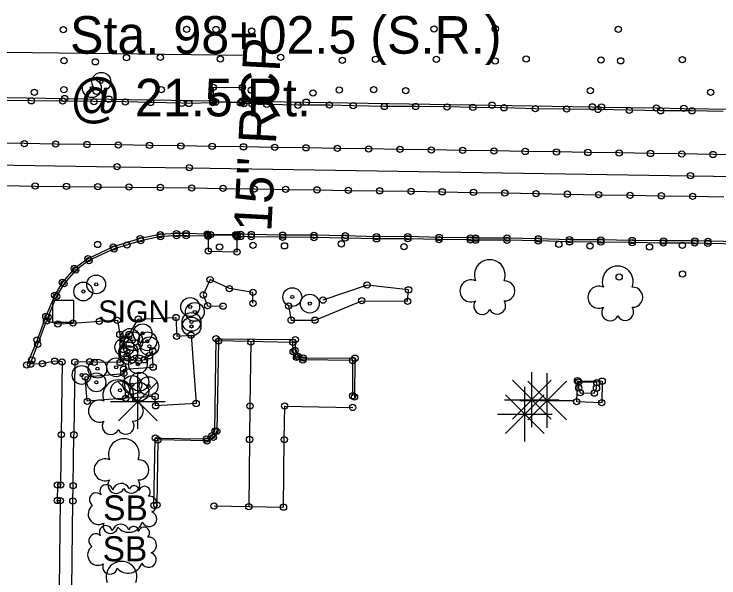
# Model space of a CAD drawing. Extents: x 20503438 to 20508873, y 7964251 to 7984667.
# Drawn here: x 20504811.1 to 20505036.2, y 7970431.1 to 7970611 of the extents above; entities that cross this region are included whole.
import ezdxf

# ---------------------------------------------------------------- set-up
doc = ezdxf.new("R2010")
doc.units = 0
for name, color, linetype in [('SurBreakLine', 7, 'Continuous'), ('SurConcreteSlab', 7, 'Continuous'), ('SurEdgeCurb', 7, 'Continuous'), ('SurEdgeRoadPaved', 7, 'Continuous'), ('SurEdgeSidewalk', 7, 'Continuous'), ('SurFenceWire', 7, 'Continuous'), ('SurHedge', 7, 'Continuous'), ('SurMiscStructureLine', 7, 'Continuous'), ('SurNaturalCells', 7, 'Continuous'), ('SurPointsNonDTM', 7, 'Continuous'), ('SurRoadPoints', 7, 'Continuous'), ('SurSurveyPoints', 7, 'Continuous'), ('SurTxtDrainage', 7, 'Continuous')]:
    doc.layers.add(name, color=color, linetype=linetype)

msp = doc.modelspace()

# ---------------------------------------------------------------- linework, layer by layer
at = {"layer": 'SurBreakLine'}
msp.add_lwpolyline([(20504771.9, 7970563.37), (20504797.86, 7970563), (20504843.99, 7970562.34), (20504867.04, 7970562.01), (20505027.11, 7970559.46), (20505056.57, 7970559.02), (20505122.33, 7970557.99), (20505134.3, 7970557.78), (20505181.34, 7970557.02), (20505190.04, 7970556.88), (20505298.19, 7970555.19), (20505381.79, 7970553.77), (20505481.65, 7970551.95), (20505538.21, 7970551.74), (20505602.69, 7970550.28), (20505659.98, 7970549.19), (20505725.91, 7970548.38)], dxfattribs=at)
at = {"layer": 'SurConcreteSlab'}
for points in [[(20504874.77, 7970583.05), (20504874.76, 7970587.67), (20504884.01, 7970587.63), (20504883.93, 7970582.84)], [(20504873.07, 7970540.53), (20504873.12, 7970535.41), (20504882.33, 7970535.14), (20504882.33, 7970540.34)], [(20504850.78, 7970513.69), (20504862.78, 7970514.2), (20504863.05, 7970508.22), (20504867.61, 7970508.56), (20504869.25, 7970486.75), (20504856.32, 7970486), (20504856.16, 7970488.98), (20504846.77, 7970488.43), (20504846.11, 7970497.7), (20504855.53, 7970498.36), (20504855.34, 7970503.57), (20504854.26, 7970501.98), (20504852.74, 7970500.7), (20504850.9, 7970500.28), (20504848.84, 7970500.61), (20504847.16, 7970501.86), (20504846.03, 7970504), (20504845.92, 7970505.68), (20504846.62, 7970507.38), (20504847.81, 7970508.81)], [(20504846.14, 7970496.36), (20504846.71, 7970488.42), (20504834.49, 7970487.47), (20504833.84, 7970495.26)], [(20504998.9, 7970493.88), (20504998.78, 7970486.99), (20504990.8, 7970487.3), (20504991.04, 7970494.03)]]:
    msp.add_lwpolyline(points, close=True, dxfattribs=at)
for points in [[(20505044.33, 7970566.08), (20505034.34, 7970566.24), (20505024.34, 7970566.4), (20505014.34, 7970566.56), (20505004.34, 7970566.72), (20504994.34, 7970566.88), (20504984.34, 7970567.04), (20504974.34, 7970567.2), (20504964.35, 7970567.36), (20504954.35, 7970567.53), (20504944.35, 7970567.69), (20504934.35, 7970567.86), (20504924.35, 7970568.02), (20504914.36, 7970568.18), (20504904.36, 7970568.35), (20504894.36, 7970568.51), (20504884.36, 7970568.68), (20504874.36, 7970568.83), (20504864.36, 7970568.97), (20504854.36, 7970569.12), (20504844.37, 7970569.27), (20504834.37, 7970569.42), (20504824.37, 7970569.57), (20504814.37, 7970569.72), (20504804.37, 7970569.87)], [(20504807.85, 7970556.29), (20504817.85, 7970556.17), (20504827.85, 7970556.05), (20504837.84, 7970555.94), (20504847.84, 7970555.82), (20504857.84, 7970555.71), (20504867.84, 7970555.55), (20504877.84, 7970555.4), (20504887.84, 7970555.25), (20504897.84, 7970555.09), (20504907.83, 7970554.94), (20504917.83, 7970554.78), (20504927.83, 7970554.63), (20504937.83, 7970554.48), (20504947.83, 7970554.32), (20504957.83, 7970554.13), (20504967.82, 7970553.95), (20504977.82, 7970553.76), (20504987.82, 7970553.58), (20504997.82, 7970553.39), (20505007.82, 7970553.21), (20505017.81, 7970553.05), (20505027.81, 7970552.9), (20505037.81, 7970552.75)], [(20504826.44, 7970500), (20504824.07, 7970500.26), (20504820.11, 7970499.45), (20504816.4, 7970499.3), (20504816.76, 7970500.66), (20504818.66, 7970505.66), (20504821.46, 7970513.14)], [(20504821.46, 7970513.14), (20504825.07, 7970512.13), (20504829.92, 7970512.42), (20504838.32, 7970512.99), (20504844.11, 7970513.33), (20504844.87, 7970508.76), (20504844.98, 7970499.83), (20504836.77, 7970499.92), (20504835.22, 7970500.07), (20504830.51, 7970499.97), (20504830.2, 7970476.76)], [(20504886.71, 7970506.41), (20504886.44, 7970485.96), (20504886.3, 7970475.27), (20504886.07, 7970453.85)], [(20504874.96, 7970454.04), (20504897.15, 7970453.65), (20504897.4, 7970475.22), (20504897.53, 7970485.95), (20504919.26, 7970485.49)]]:
    msp.add_lwpolyline(points, dxfattribs=at)
at = {"layer": 'SurEdgeCurb'}
for points in [[(20505037.59, 7970579.95), (20505027.59, 7970580.17), (20505017.59, 7970580.18), (20505007.59, 7970580.34), (20504997.59, 7970580.61), (20504987.59, 7970580.75), (20504977.59, 7970580.83), (20504967.6, 7970581.14), (20504957.6, 7970581.26), (20504949.37, 7970581.42), (20504939.37, 7970581.54), (20504929.37, 7970581.56), (20504919.38, 7970581.81), (20504911.81, 7970582), (20504901.81, 7970581.95), (20504891.81, 7970582.22), (20504887.15, 7970582.36), (20504884.51, 7970582.49), (20504883.4, 7970582.67), (20504875.45, 7970582.95), (20504874.56, 7970582.74), (20504866.97, 7970582.51), (20504864.69, 7970582.59), (20504854.69, 7970582.84), (20504846.61, 7970583.02), (20504836.61, 7970583.12), (20504826.61, 7970583.3), (20504816.61, 7970583.36), (20504807.55, 7970583.5)], [(20505042.68, 7970538.3), (20505032.68, 7970538.53), (20505028.5, 7970538.65), (20505018.49, 7970538.65), (20505008.49, 7970538.78), (20504998.49, 7970538.95), (20504988.49, 7970539.04), (20504978.5, 7970539.31), (20504968.5, 7970539.55), (20504958.49, 7970539.52), (20504956.87, 7970539.58), (20504946.85, 7970539.74), (20504936.86, 7970540.01), (20504926.86, 7970540), (20504916.86, 7970540.3), (20504906.86, 7970540.43), (20504896.86, 7970540.49), (20504886.86, 7970540.69), (20504883.43, 7970540.75), (20504882.42, 7970540.62), (20504881.88, 7970540.59), (20504873.92, 7970540.65), (20504872.81, 7970540.8), (20504866.07, 7970540.99), (20504862.96, 7970540.98), (20504857.78, 7970540.66), (20504851.38, 7970539.38), (20504842.8, 7970536.73), (20504834.7, 7970532.95), (20504830.35, 7970529.85), (20504826.5, 7970525.39), (20504824.07, 7970521.29), (20504821.26, 7970514.59), (20504818.45, 7970507), (20504815.13, 7970499.07)], [(20504873.07, 7970540.12), (20504866.07, 7970540.3), (20504862.99, 7970540.3), (20504857.88, 7970540.01), (20504851.54, 7970538.72), (20504843.05, 7970536.09), (20504835.03, 7970532.35), (20504830.79, 7970529.35), (20504827.07, 7970525.01), (20504824.68, 7970520.99), (20504821.93, 7970514.32), (20504821.46, 7970513.14)], [(20505042.66, 7970537.61), (20505032.67, 7970537.84), (20505028.48, 7970537.97), (20505018.48, 7970537.95), (20505008.48, 7970538.11), (20504998.48, 7970538.27), (20504988.48, 7970538.36), (20504978.48, 7970538.62), (20504968.49, 7970538.86), (20504958.49, 7970538.88), (20504956.84, 7970538.94), (20504946.84, 7970539.07), (20504936.84, 7970539.35), (20504926.84, 7970539.32), (20504916.84, 7970539.57), (20504906.85, 7970539.72), (20504896.85, 7970539.81), (20504886.85, 7970540), (20504883.49, 7970540.07), (20504882.33, 7970539.93)], [(20504855.77, 7970454.24), (20504856.18, 7970475.73), (20504872.49, 7970475.43), (20504874.33, 7970476.45), (20504875.24, 7970478), (20504875.59, 7970507.41), (20504900.91, 7970507.13), (20504900.83, 7970503.68), (20504901.72, 7970501.84), (20504903.45, 7970501.3), (20504919.96, 7970501.22), (20504919.83, 7970488.82)], [(20504919.26, 7970489.19), (20504919.25, 7970500.48), (20504903.31, 7970500.65), (20504901.3, 7970501.49), (20504900.23, 7970503.3), (20504900.13, 7970506.25), (20504876.44, 7970506.73), (20504875.84, 7970477.88), (20504874.77, 7970475.96), (20504872.74, 7970474.79), (20504857.03, 7970475.13), (20504856.71, 7970454.33)]]:
    msp.add_lwpolyline(points, dxfattribs=at)
at = {"layer": 'SurEdgeRoadPaved'}
for points in [[(20504727.85, 7970585.32), (20504737.85, 7970585.29), (20504744.25, 7970585.34), (20504754.25, 7970585.2), (20504764.26, 7970584.93), (20504772.2, 7970585.02), (20504827.27, 7970584.09), (20504841.35, 7970583.88), (20504874.77, 7970583.4)], [(20504883.94, 7970583.27), (20504904.39, 7970582.93), (20504963.72, 7970581.98), (20504995.8, 7970581.43), (20504998.71, 7970581.38), (20505016.18, 7970581.08), (20505025.01, 7970580.93), (20505048.57, 7970580.55), (20505051.52, 7970580.5), (20505057.41, 7970580.41), (20505084.04, 7970579.95), (20505175.4, 7970578.44)]]:
    msp.add_lwpolyline(points, dxfattribs=at)
at = {"layer": 'SurEdgeSidewalk'}
msp.add_lwpolyline([(20504826.44, 7970500), (20504826.17, 7970476.78), (20504825.95, 7970460.74), (20504824.96, 7970460.73), (20504824.89, 7970455.79), (20504825.87, 7970455.75), (20504825.55, 7970427.65), (20504829.53, 7970427.55), (20504829.88, 7970455.61), (20504829.97, 7970460.55), (20504830.2, 7970476.76)], dxfattribs=at)
at = {"layer": 'SurFenceWire'}
msp.add_lwpolyline([(20504884.71, 7970597.81), (20504782.91, 7970599.08), (20504566.31, 7970601.59), (20504471.49, 7970602.55)], dxfattribs=at)
at = {"layer": 'SurHedge'}
for points in [[(20504887.37, 7970518.73), (20504887.38, 7970522.2), (20504879.86, 7970523.43), (20504873.71, 7970526.29), (20504871.54, 7970521.42), (20504872.91, 7970517.95), (20504877.83, 7970517.82)], [(20504898.78, 7970517.9), (20504899.61, 7970513.36), (20504907.21, 7970513.34), (20504922.11, 7970519.56), (20504936.77, 7970519.39), (20504937.08, 7970523.04), (20504923.85, 7970524.54), (20504909.73, 7970519.75)]]:
    msp.add_lwpolyline(points, dxfattribs=at)
at = {"layer": 'SurMiscStructureLine'}
msp.add_lwpolyline([(20504991.35, 7970493.6), (20504991.38, 7970491.76), (20504991.89, 7970490.2), (20504996.4, 7970490.04), (20504997.11, 7970491.65), (20504997.22, 7970493.43)], close=True, dxfattribs=at)
at = {"layer": 'SurNaturalCells'}
for p, q in [((20504976.49, 7970479.23), (20504976.49, 7970496.71)), ((20504981.31, 7970478.97), (20504981.31, 7970496.45)), ((20504850.6, 7970478.67), (20504850.6, 7970496.15)), ((20504970.31, 7970481.79), (20504982.67, 7970494.15)), ((20504982.67, 7970481.79), (20504970.31, 7970494.15)), ((20504844.42, 7970481.23), (20504856.78, 7970493.59)), ((20504856.78, 7970481.23), (20504844.42, 7970493.59)), ((20504974.22, 7970474.59), (20504974.22, 7970492.07)), ((20504975.13, 7970481.53), (20504987.49, 7970493.89)), ((20504987.49, 7970481.53), (20504975.13, 7970493.89)), ((20504968.04, 7970477.15), (20504980.4, 7970489.51)), ((20504980.4, 7970477.15), (20504968.04, 7970489.51)), ((20504841.86, 7970487.41), (20504859.34, 7970487.41)), ((20504850.6, 7970487.41), (20504850.6, 7970487.41)), ((20504967.75, 7970487.97), (20504985.23, 7970487.97)), ((20504972.57, 7970487.71), (20504990.05, 7970487.71)), ((20504976.49, 7970487.97), (20504976.49, 7970487.97)), ((20504981.31, 7970487.71), (20504981.31, 7970487.71)), ((20504965.48, 7970483.33), (20504982.96, 7970483.33)), ((20504974.22, 7970483.33), (20504974.22, 7970483.33))]:
    msp.add_line(p, q, dxfattribs=at)
for centre, radius, start, end in [((20504963.02, 7970527.71), 4.92, 338.2051, 201.7949), ((20505003.88, 7970525.7), 4.92, 338.2051, 201.7949), ((20504957, 7970522.68), 3.51, 65.4824, 294.5175), ((20504967.82, 7970522.68), 3.21, 265.9982, 94.0018), ((20504997.86, 7970520.67), 3.51, 65.4824, 294.5175), ((20505008.68, 7970520.67), 3.21, 265.9982, 94.0018), ((20504960.59, 7970517.86), 2.68, 142.7501, 335.3223), ((20504965.41, 7970517.94), 2.67, 206.5242, 35.4033), ((20505001.45, 7970515.85), 2.68, 142.7501, 335.3223), ((20505006.27, 7970515.93), 2.67, 206.5242, 35.4033), ((20504844.38, 7970489.37), 4.92, 338.2051, 201.7949), ((20504838.36, 7970484.34), 3.51, 65.4824, 294.5175), ((20504849.18, 7970484.34), 3.21, 265.9982, 94.0018), ((20504841.95, 7970479.52), 2.68, 142.7501, 335.3223), ((20504846.77, 7970479.6), 2.67, 206.5242, 35.4033), ((20504846.17, 7970470.6), 4.92, 338.2051, 201.7949), ((20504840.15, 7970465.57), 3.51, 65.4824, 294.5175), ((20504850.97, 7970465.57), 3.21, 265.9982, 94.0018), ((20504840.59, 7970458.74), 2.08, 10.5948, 214.3611), ((20504843.74, 7970460.75), 2.68, 142.7501, 335.3223), ((20504845.35, 7970458.44), 2.81, 22.6036, 165.7836), ((20504848.56, 7970460.83), 2.67, 206.5242, 35.4033), ((20504849.43, 7970458.94), 1.59, 0.4605, 158.7839), ((20504852.77, 7970458.53), 1.8, 311.3936, 166.4114), ((20504837.34, 7970456.02), 2.18, 45.3455, 236.8073), ((20504854.15, 7970454.59), 2.6, 290.9039, 94.3687), ((20504838.1, 7970451.49), 3.34, 125.8289, 299.2848), ((20504854.25, 7970449.9), 2.42, 204.8294, 69.8871), ((20504840.42, 7970445.69), 2.08, 10.5948, 214.3611), ((20504841.91, 7970447.66), 2.36, 157.0258, 349.7602), ((20504845.18, 7970445.39), 2.81, 22.6036, 165.7836), ((20504847.7, 7970450.16), 4.53, 220.0183, 343.6977), ((20504849.26, 7970445.89), 1.59, 0.4605, 158.7839), ((20504852.6, 7970445.48), 1.8, 311.3936, 166.4114), ((20504837.17, 7970442.97), 2.18, 45.3455, 236.8073), ((20504853.98, 7970441.54), 2.6, 290.9039, 94.3687), ((20504837.93, 7970438.44), 3.34, 125.8289, 299.2848), ((20504854.08, 7970436.85), 2.42, 204.8294, 69.8871), ((20504841.74, 7970434.61), 2.36, 157.0258, 349.7602), ((20504845.43, 7970431.43), 4.92, 338.2051, 201.7949), ((20504847.53, 7970437.11), 4.53, 220.0183, 343.6977)]:
    msp.add_arc(centre, radius, start, end, dxfattribs=at)
at = {"layer": 'SurPointsNonDTM'}
for centre in [(20504998.55, 7970596.39), (20504873.71, 7970526.29), (20504923.85, 7970524.54), (20504879.86, 7970523.43), (20504887.38, 7970522.2), (20504937.08, 7970523.04), (20504871.54, 7970521.42), (20504872.91, 7970517.95), (20504877.83, 7970517.82), (20504887.37, 7970518.73), (20504898.78, 7970517.9), (20504909.73, 7970519.75), (20504922.11, 7970519.56), (20504936.77, 7970519.39), (20504899.61, 7970513.36), (20504907.21, 7970513.34), (20504991.35, 7970493.6), (20504997.22, 7970493.43), (20504991.38, 7970491.76), (20504997.11, 7970491.65), (20504991.89, 7970490.2), (20504996.4, 7970490.04)]:
    msp.add_circle(centre, 1, dxfattribs=at)
at = {"layer": 'SurRoadPoints'}
msp.add_lwpolyline([(20504826.76, 7970512.72), (20504826.76, 7970512.72), (20504830.19, 7970512.72), (20504830.19, 7970519.58), (20504823.33, 7970519.58), (20504823.33, 7970512.72), (20504826.76, 7970512.72)], dxfattribs=at)
for centre, radius in [((20504838.98, 7970589.44), 3), ((20504835.94, 7970587.39), 3), ((20504838.98, 7970589.44), 0.5), ((20504835.94, 7970587.39), 0.5), ((20504837.33, 7970524.76), 3), ((20504833.21, 7970522.5), 3), ((20504837.33, 7970524.76), 0.5), ((20504899.95, 7970520.72), 3), ((20504833.21, 7970522.5), 0.5), ((20504899.95, 7970520.72), 0.5), ((20504905.55, 7970518.62), 3), ((20504867.35, 7970517.57), 3), ((20504868.83, 7970515.98), 3), ((20504905.55, 7970518.62), 0.5), ((20504867.35, 7970517.57), 0.5), ((20504868.83, 7970515.98), 0.5), ((20504867.76, 7970511.34), 3), ((20504867.77, 7970512.79), 3), ((20504852.15, 7970509.17), 3), ((20504867.77, 7970512.79), 0.5), ((20504848.16, 7970507.71), 3), ((20504867.76, 7970511.34), 0.5), ((20504846.32, 7970504.73), 3), ((20504849.23, 7970506.62), 3), ((20504848.16, 7970507.71), 0.5), ((20504853.69, 7970506.61), 3), ((20504854.32, 7970505.02), 3), ((20504852.15, 7970509.17), 0.5), ((20504847.6, 7970503.36), 3), ((20504847.62, 7970502.23), 3), ((20504846.32, 7970504.73), 0.5), ((20504849.23, 7970506.62), 0.5), ((20504853.69, 7970506.61), 0.5), ((20504854.32, 7970505.02), 0.5), ((20504847.6, 7970503.36), 0.5), ((20504837.73, 7970497.86), 3), ((20504843.7, 7970498.3), 3), ((20504847.62, 7970502.23), 0.5), ((20504850.64, 7970499.29), 3), ((20504832.67, 7970495.86), 3), ((20504843.7, 7970498.3), 0.5), ((20504850.64, 7970499.29), 0.5), ((20504832.67, 7970495.86), 0.5), ((20504837.38, 7970493.5), 3), ((20504837.73, 7970497.86), 0.5), ((20504851.14, 7970493.71), 3), ((20504837.38, 7970493.5), 0.5), ((20504844.95, 7970490.95), 3), ((20504848.87, 7970492.69), 3), ((20504851.14, 7970493.71), 0.5), ((20504854.05, 7970492.31), 3), ((20504851.13, 7970490.51), 3), ((20504848.87, 7970492.69), 0.5), ((20504854.05, 7970492.31), 0.5), ((20504844.95, 7970490.95), 0.5), ((20504851.13, 7970490.51), 0.5)]:
    msp.add_circle(centre, radius, dxfattribs=at)
at = {"layer": 'SurSurveyPoints'}
for centre in [(20504826.8, 7970606.04), (20504866.21, 7970606.17), (20504875.57, 7970606.13), (20504886.99, 7970605.62), (20504945.22, 7970606.28), (20504964.82, 7970606.33), (20505004.09, 7970606.15), (20504847.01, 7970597.14), (20504857.83, 7970597.26), (20504876.95, 7970596.71), (20504896.23, 7970597.26), (20504926.52, 7970596.57), (20504945.93, 7970596.57), (20504974.65, 7970596.69), (20505024.54, 7970596.52), (20504827.07, 7970596.19), (20504837.09, 7970595.81), (20504915.93, 7970596.29), (20504964.75, 7970596.09), (20505004.84, 7970596.13), (20504874.76, 7970587.67), (20504884.01, 7970587.63), (20504817.58, 7970586.08), (20504827.01, 7970586.93), (20504837.41, 7970586.38), (20504858.12, 7970586.95), (20504886.88, 7970586.76), (20504906.59, 7970585.88), (20504914.94, 7970586.84), (20504925.96, 7970586.93), (20504936.18, 7970586.58), (20504995.17, 7970586.6), (20505033.53, 7970586.07), (20504816.61, 7970583.36), (20504826.61, 7970583.3), (20504827.27, 7970584.09), (20504836.61, 7970583.12), (20504841.35, 7970583.88), (20504846.61, 7970583.02), (20504874.54, 7970583.43), (20504874.77, 7970583.4), (20504874.77, 7970583.05), (20504883.94, 7970583.27), (20504854.69, 7970582.84), (20504864.69, 7970582.59), (20504866.97, 7970582.51), (20504874.56, 7970582.74), (20504875.45, 7970582.95), (20504883.4, 7970582.67), (20504883.93, 7970582.84), (20504884.51, 7970582.49), (20504887.15, 7970582.36), (20504891.81, 7970582.22), (20504901.81, 7970581.95), (20504904.39, 7970582.93), (20504911.81, 7970582), (20504919.38, 7970581.81), (20504929.37, 7970581.56), (20504939.37, 7970581.54), (20504949.37, 7970581.42), (20504957.6, 7970581.26), (20504963.72, 7970581.98), (20504967.6, 7970581.14), (20504977.59, 7970580.83), (20504987.59, 7970580.75), (20504995.8, 7970581.43), (20504998.71, 7970581.38), (20505016.18, 7970581.08), (20505025.01, 7970580.93), (20504997.59, 7970580.61), (20505007.59, 7970580.34), (20505017.59, 7970580.18), (20505027.59, 7970580.17), (20504814.37, 7970569.72), (20504824.37, 7970569.57), (20504834.37, 7970569.42), (20504844.37, 7970569.27), (20504854.36, 7970569.12), (20504864.36, 7970568.97), (20504874.36, 7970568.83), (20504884.36, 7970568.68), (20504894.36, 7970568.51), (20504904.36, 7970568.35), (20504914.36, 7970568.18), (20504924.35, 7970568.02), (20504934.35, 7970567.86), (20504944.35, 7970567.69), (20504954.35, 7970567.53), (20504964.35, 7970567.36), (20504974.34, 7970567.2), (20504984.34, 7970567.04), (20504994.34, 7970566.88), (20505004.34, 7970566.72), (20505014.34, 7970566.56), (20505024.34, 7970566.4), (20505034.34, 7970566.24), (20504843.99, 7970562.34), (20504867.04, 7970562.01), (20505027.11, 7970559.46), (20504817.85, 7970556.17), (20504827.85, 7970556.05), (20504837.84, 7970555.94), (20504847.84, 7970555.82), (20504857.84, 7970555.71), (20504867.84, 7970555.55), (20504877.84, 7970555.4), (20504887.84, 7970555.25), (20504897.84, 7970555.09), (20504907.83, 7970554.94), (20504917.83, 7970554.78), (20504927.83, 7970554.63), (20504937.83, 7970554.48), (20504947.83, 7970554.32), (20504957.83, 7970554.13), (20504967.82, 7970553.95), (20504977.82, 7970553.76), (20504987.82, 7970553.58), (20504997.82, 7970553.39), (20505007.82, 7970553.21), (20505017.81, 7970553.05), (20505027.81, 7970552.9), (20504857.78, 7970540.66), (20504862.96, 7970540.98), (20504862.99, 7970540.3), (20504866.07, 7970540.99), (20504866.07, 7970540.3), (20504872.81, 7970540.8), (20504873.07, 7970540.53), (20504873.92, 7970540.65), (20504881.88, 7970540.59), (20504882.33, 7970540.34), (20504882.42, 7970540.62), (20504883.43, 7970540.75), (20504886.86, 7970540.69), (20504896.86, 7970540.49), (20504906.86, 7970540.43), (20504916.86, 7970540.3), (20504851.38, 7970539.38), (20504851.54, 7970538.72), (20504857.88, 7970540.01), (20504873.07, 7970540.12), (20504882.33, 7970539.93), (20504883.49, 7970540.07), (20504886.85, 7970540), (20504896.85, 7970539.81), (20504906.85, 7970539.72), (20504916.84, 7970539.57), (20504926.84, 7970539.32), (20504926.86, 7970540), (20504936.84, 7970539.35), (20504936.86, 7970540.01), (20504946.84, 7970539.07), (20504946.85, 7970539.74), (20504956.84, 7970538.94), (20504956.87, 7970539.58), (20504958.49, 7970539.52), (20504958.49, 7970538.88), (20504968.49, 7970538.86), (20504968.5, 7970539.55), (20504978.48, 7970538.62), (20504978.5, 7970539.31), (20504988.48, 7970538.36), (20504988.49, 7970539.04), (20504998.48, 7970538.27), (20504998.49, 7970538.95), (20505008.48, 7970538.11), (20505008.49, 7970538.78), (20505018.49, 7970538.65), (20505028.48, 7970537.97), (20505028.5, 7970538.65), (20505032.68, 7970538.53), (20504837.8, 7970537.5), (20504842.8, 7970536.73), (20504843.05, 7970536.09), (20504847.19, 7970537.32), (20504876.72, 7970536.68), (20504887.4, 7970537.26), (20504897.46, 7970537.08), (20504915.62, 7970537.7), (20504935.63, 7970536.84), (20504985.07, 7970537.56), (20504995.03, 7970537.02), (20505014.03, 7970536.71), (20505018.48, 7970537.95), (20505024.53, 7970537.21), (20505032.67, 7970537.84), (20504873.12, 7970535.41), (20504882.33, 7970535.14), (20504834.7, 7970532.95), (20504835.03, 7970532.35), (20504830.35, 7970529.85), (20504830.79, 7970529.35), (20505004.35, 7970527.13), (20505024.56, 7970528.06), (20504826.5, 7970525.39), (20504827.07, 7970525.01), (20504824.07, 7970521.29), (20504824.68, 7970520.99), (20504821.26, 7970514.59), (20504821.93, 7970514.32), (20504844.11, 7970513.33), (20504850.78, 7970513.69), (20504862.78, 7970514.2), (20504821.46, 7970513.14), (20504825.07, 7970512.13), (20504829.92, 7970512.42), (20504838.32, 7970512.99), (20504844.87, 7970508.76), (20504847.81, 7970508.81), (20504818.45, 7970507), (20504846.62, 7970507.38), (20504863.05, 7970508.22), (20504867.61, 7970508.56), (20504875.59, 7970507.41), (20504876.44, 7970506.73), (20504900.91, 7970507.13), (20504818.66, 7970505.66), (20504845.92, 7970505.68), (20504886.71, 7970506.41), (20504900.13, 7970506.25), (20504846.03, 7970504), (20504854.26, 7970501.98), (20504855.34, 7970503.57), (20504900.23, 7970503.3), (20504900.83, 7970503.68), (20504816.76, 7970500.66), (20504824.07, 7970500.26), (20504826.44, 7970500), (20504830.51, 7970499.97), (20504835.22, 7970500.07), (20504836.77, 7970499.92), (20504844.98, 7970499.83), (20504847.16, 7970501.86), (20504848.84, 7970500.61), (20504850.9, 7970500.28), (20504852.74, 7970500.7), (20504901.3, 7970501.49), (20504901.72, 7970501.84), (20504903.31, 7970500.65), (20504903.45, 7970501.3), (20504919.25, 7970500.48), (20504919.96, 7970501.22), (20504815.13, 7970499.07), (20504816.4, 7970499.3), (20504820.11, 7970499.45), (20504846.11, 7970497.7), (20504855.53, 7970498.36), (20504833.84, 7970495.26), (20504846.14, 7970496.36), (20504991.04, 7970494.03), (20504998.9, 7970493.88), (20504856.16, 7970488.98), (20504919.26, 7970489.19), (20504919.83, 7970488.82), (20504834.49, 7970487.47), (20504846.71, 7970488.42), (20504846.77, 7970488.43), (20504869.25, 7970486.75), (20504990.8, 7970487.3), (20504998.78, 7970486.99), (20504856.32, 7970486), (20504886.44, 7970485.96), (20504897.53, 7970485.95), (20504919.26, 7970485.49), (20504875.24, 7970478), (20504875.84, 7970477.88), (20504826.17, 7970476.78), (20504830.2, 7970476.76), (20504856.18, 7970475.73), (20504857.03, 7970475.13), (20504872.49, 7970475.43), (20504874.33, 7970476.45), (20504874.77, 7970475.96), (20504886.3, 7970475.27), (20504897.4, 7970475.22), (20504872.74, 7970474.79), (20504824.96, 7970460.73), (20504825.95, 7970460.74), (20504829.97, 7970460.55), (20504824.89, 7970455.79), (20504825.87, 7970455.75), (20504829.88, 7970455.61), (20504855.77, 7970454.24), (20504856.71, 7970454.33), (20504874.96, 7970454.04), (20504886.07, 7970453.85), (20504897.15, 7970453.65)]:
    msp.add_circle(centre, 1, dxfattribs=at)

# ---------------------------------------------------------------- texts
at = {"layer": 'SurNaturalCells'}
for p in [(20504839.55, 7970449.44), (20504839.38, 7970436.39)]:
    msp.add_text('SB', height=7.995, rotation=360, dxfattribs=at).set_placement(p)
at = {"layer": 'SurRoadPoints'}
msp.add_text('SIGN', height=6.995, rotation=360, dxfattribs=at).set_placement((20504837.97, 7970512.65))
at = {"layer": 'SurTxtDrainage'}
for s, p in [('Sta. 98+02.5 (S.R.)', (20504828.96, 7970598.4)), ('@ 21.5 Rt.', (20504828.96, 7970578.4))]:
    msp.add_text(s, height=12, dxfattribs=at).set_placement(p)
msp.add_text('15" RCP', height=12, rotation=86.991, dxfattribs=at).set_placement((20504893.23, 7970541.39))

doc.saveas('drawing.dxf')
